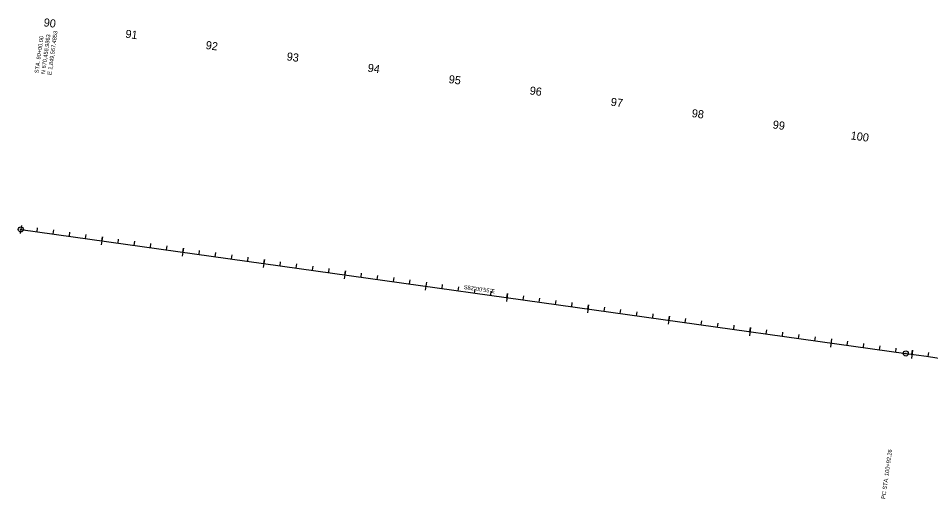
# Model space of a CAD drawing. Extents: x 1849564 to 1851966, y 666816 to 670715.
# Drawn here: x 1849564 to 1850680, y 670128 to 670715 of the extents above; entities that cross this region are included whole.
import ezdxf

# ---------------------------------------------------------------- set-up
doc = ezdxf.new("R2010")
doc.units = 0
for name, color, linetype in [('CONCEPT - PAVEMENT MARKING - Crosswalk Long', 7, 'Continuous'), ('CONCEPT - PAVEMENT MARKING - Crosswalk Parallel', 7, 'Continuous'), ('CONCEPT - PAVEMENT MARKING - Stop Bar', 7, 'Continuous'), ('CONCEPT - PAVEMENT MARKING - Striping - Yellow', 7, 'Continuous'), ('Default', 7, 'Continuous'), ('DES - DRG - Special Ditches', 7, 'Continuous')]:
    doc.layers.add(name, color=color, linetype=linetype)

msp = doc.modelspace()

# ---------------------------------------------------------------- linework, layer by layer
at = {"layer": 'CONCEPT - PAVEMENT MARKING - Stop Bar'}
for p, q in [((1849568.2, 670461.9), (1849566.8, 670452)), ((1849587.3, 670454.2), (1849588, 670459.1)), ((1849607.1, 670451.4), (1849607.8, 670456.4)), ((1849626.9, 670448.7), (1849627.6, 670453.6)), ((1849646.7, 670445.9), (1849647.4, 670450.8)), ((1849667.2, 670448), (1849665.8, 670438.1)), ((1849686.3, 670440.3), (1849687, 670445.2)), ((1849706.1, 670437.5), (1849706.8, 670442.5)), ((1849725.9, 670434.8), (1849726.6, 670439.7)), ((1849745.7, 670432), (1849746.4, 670436.9)), ((1849766.2, 670434.2), (1849764.9, 670424.3)), ((1849785.4, 670426.4), (1849786, 670431.4)), ((1849805.2, 670423.6), (1849805.9, 670428.6)), ((1849825, 670420.9), (1849825.7, 670425.8)), ((1849844.8, 670418.1), (1849845.5, 670423)), ((1849865.3, 670420.3), (1849863.9, 670410.4)), ((1849884.4, 670412.5), (1849885.1, 670417.5)), ((1849904.2, 670409.8), (1849904.9, 670414.7)), ((1849924, 670407), (1849924.7, 670411.9)), ((1849943.8, 670404.2), (1849944.5, 670409.1)), ((1849964.3, 670406.4), (1849962.9, 670396.5)), ((1849983.4, 670398.6), (1849984.1, 670403.6)), ((1850003.2, 670395.9), (1850003.9, 670400.8)), ((1850023, 670393.1), (1850023.7, 670398)), ((1850042.8, 670390.3), (1850043.5, 670395.2)), ((1850063.3, 670392.5), (1850061.9, 670382.6)), ((1850082.4, 670384.8), (1850083.1, 670389.7)), ((1850102.2, 670382), (1850102.9, 670386.9)), ((1850122.1, 670379.2), (1850122.7, 670384.1)), ((1850141.9, 670376.4), (1850142.6, 670381.3)), ((1850162.4, 670378.6), (1850161, 670368.7)), ((1850181.5, 670370.9), (1850182.2, 670375.8)), ((1850201.3, 670368.1), (1850202, 670373)), ((1850221.1, 670365.3), (1850221.8, 670370.2)), ((1850240.9, 670362.5), (1850241.6, 670367.5)), ((1850261.4, 670364.7), (1850260, 670354.8)), ((1850280.5, 670357), (1850281.2, 670361.9)), ((1850300.3, 670354.2), (1850301, 670359.1)), ((1850320.1, 670351.4), (1850320.8, 670356.3)), ((1850339.9, 670348.6), (1850340.6, 670353.6)), ((1850360.4, 670350.8), (1850359, 670340.9)), ((1850379.5, 670343.1), (1850380.2, 670348)), ((1850399.3, 670340.3), (1850400, 670345.2)), ((1850419.1, 670337.5), (1850419.8, 670342.5)), ((1850439, 670334.7), (1850439.6, 670339.7)), ((1850459.5, 670336.9), (1850458.1, 670327)), ((1850478.6, 670329.2), (1850479.3, 670334.1)), ((1850498.4, 670326.4), (1850499.1, 670331.3)), ((1850518.2, 670323.6), (1850518.9, 670328.6)), ((1850538, 670320.9), (1850538.7, 670325.8)), ((1850558.5, 670323), (1850557.1, 670313.1)), ((1850577.6, 670315.3), (1850578.3, 670320.2)), ((1850597.4, 670312.5), (1850598.1, 670317.5)), ((1850617.2, 670309.7), (1850617.9, 670314.7)), ((1850637, 670307), (1850637.7, 670311.9)), ((1850657.5, 670309.1), (1850656.1, 670299.2)), ((1850676.6, 670301.4), (1850677.3, 670306.4))]:
    msp.add_line(p, q, dxfattribs=at)
at = {"layer": 'CONCEPT - PAVEMENT MARKING - Striping - Yellow'}
for p, q in [((1849568.2, 670461.9), (1849566.8, 670452)), ((1849666.5, 670443.1), (1849667.2, 670448)), ((1849765.5, 670429.2), (1849766.2, 670434.1)), ((1849864.6, 670415.3), (1849865.3, 670420.2)), ((1849963.6, 670401.4), (1849964.3, 670406.4)), ((1850063.3, 670392.5), (1850061.9, 670382.6)), ((1850161.7, 670373.6), (1850162.4, 670378.6)), ((1850260.7, 670359.7), (1850261.4, 670364.7)), ((1850359.7, 670345.9), (1850360.4, 670350.8)), ((1850458.8, 670332), (1850459.5, 670336.9)), ((1850558.5, 670323), (1850557.1, 670313.1)), ((1850656.8, 670304.2), (1850657.5, 670309.1))]:
    msp.add_line(p, q, dxfattribs=at)
for centre, radius in [((1849567.5, 670457), 3.14), ((1849567.5, 670457), 0.33), ((1850649.2, 670305.3), 3.14), ((1850649.2, 670305.3), 0.33)]:
    msp.add_circle(centre, radius, dxfattribs=at)
at = {"layer": 'Default'}
msp.add_line((1849567.5, 670457), (1850649.2, 670305.3), dxfattribs=at)
msp.add_arc((1853826.3, 692955.2), 22871.6, 262.01516, 263.03621, dxfattribs=at)
at = {"layer": 'DES - DRG - Special Ditches'}
msp.add_line((1849567.5, 670457), (1850649.2, 670305.3), dxfattribs=at)
msp.add_arc((1853826.3, 692955.2), 22871.6, 262.01516, 263.03621, dxfattribs=at)

# ---------------------------------------------------------------- texts
at = {"layer": 'CONCEPT - PAVEMENT MARKING - Crosswalk Long'}
for s, p in [('100+92.26', (1850628.1, 670155.2)), (' STA. ', (1850625.5, 670136.6)), ('PC', (1850624.2, 670127))]:
    msp.add_text(s, height=4.98, rotation=82.0152, dxfattribs=at).set_placement(p)
at = {"layer": 'CONCEPT - PAVEMENT MARKING - Crosswalk Parallel'}
for s, rotation, p in [('90+00.00', 82.0152, (1849591.4, 670664.6)), ('670,456.9863', 82.0152, (1849597.9, 670653.6)), ('1,849,567.4853', 82.0152, (1849605.8, 670652.1)), ('STA. ', 82.0152, (1849589.1, 670647.8)), ('N ', 82.0152, (1849597, 670646.7)), ('E ', 82.0152, (1849604.9, 670645.6)), ('S82°00\'55"E', 352.0152, (1850108.7, 670384.1))]:
    msp.add_text(s, height=4.98, rotation=rotation, dxfattribs=at).set_placement(p)
at = {"layer": 'CONCEPT - PAVEMENT MARKING - Stop Bar'}
for s, p in [('90', (1849594.9, 670705.6)), ('91', (1849694.8, 670691.6)), ('92', (1849793, 670677.8)), ('93', (1849892, 670663.9)), ('94', (1849991, 670650)), ('95', (1850090, 670636.1)), ('96', (1850189, 670622.2)), ('97', (1850288.1, 670608.4)), ('98', (1850387.1, 670594.5)), ('99', (1850486.1, 670580.6)), ('100', (1850581.4, 670567.2))]:
    msp.add_text(s, height=9.96, rotation=352.0152, dxfattribs=at).set_placement(p)
at = {"layer": 'CONCEPT - PAVEMENT MARKING - Striping - Yellow'}
for s, p in [('90', (1849594.9, 670705.6)), ('95', (1850090, 670636.1)), ('100', (1850581.4, 670567.2))]:
    msp.add_text(s, height=9.96, rotation=352.0152, dxfattribs=at).set_placement(p)

doc.saveas('drawing.dxf')
